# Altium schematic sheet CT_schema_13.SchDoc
size 741 x 377 mm
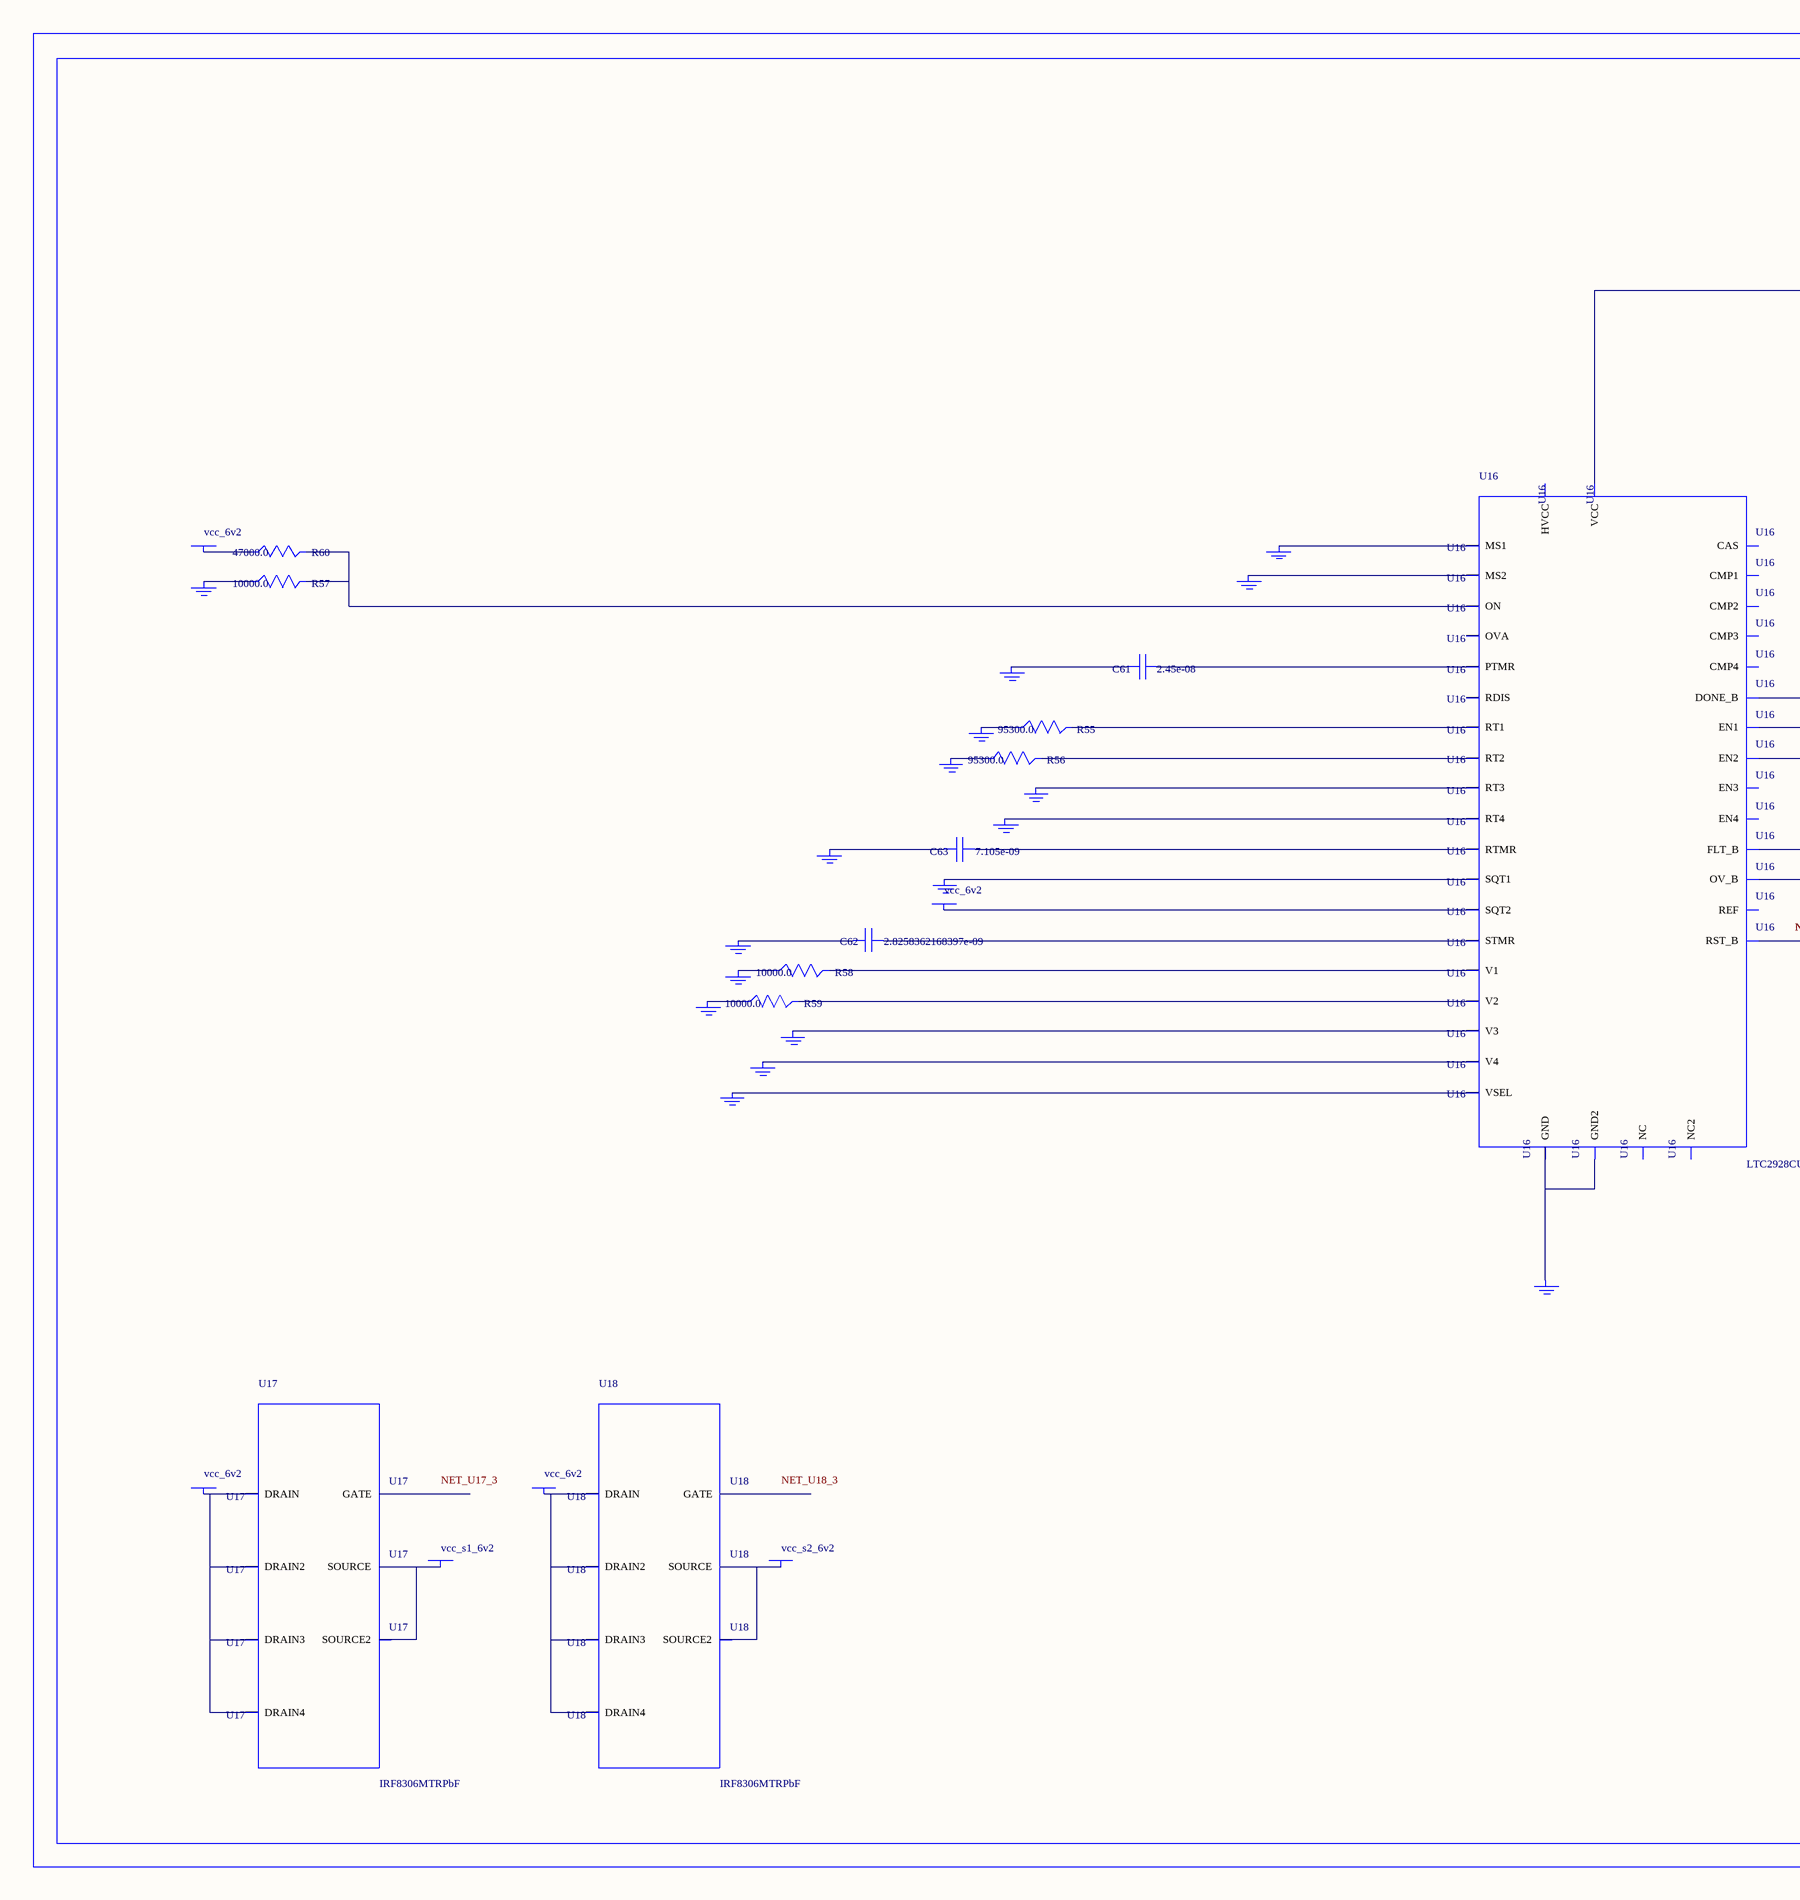
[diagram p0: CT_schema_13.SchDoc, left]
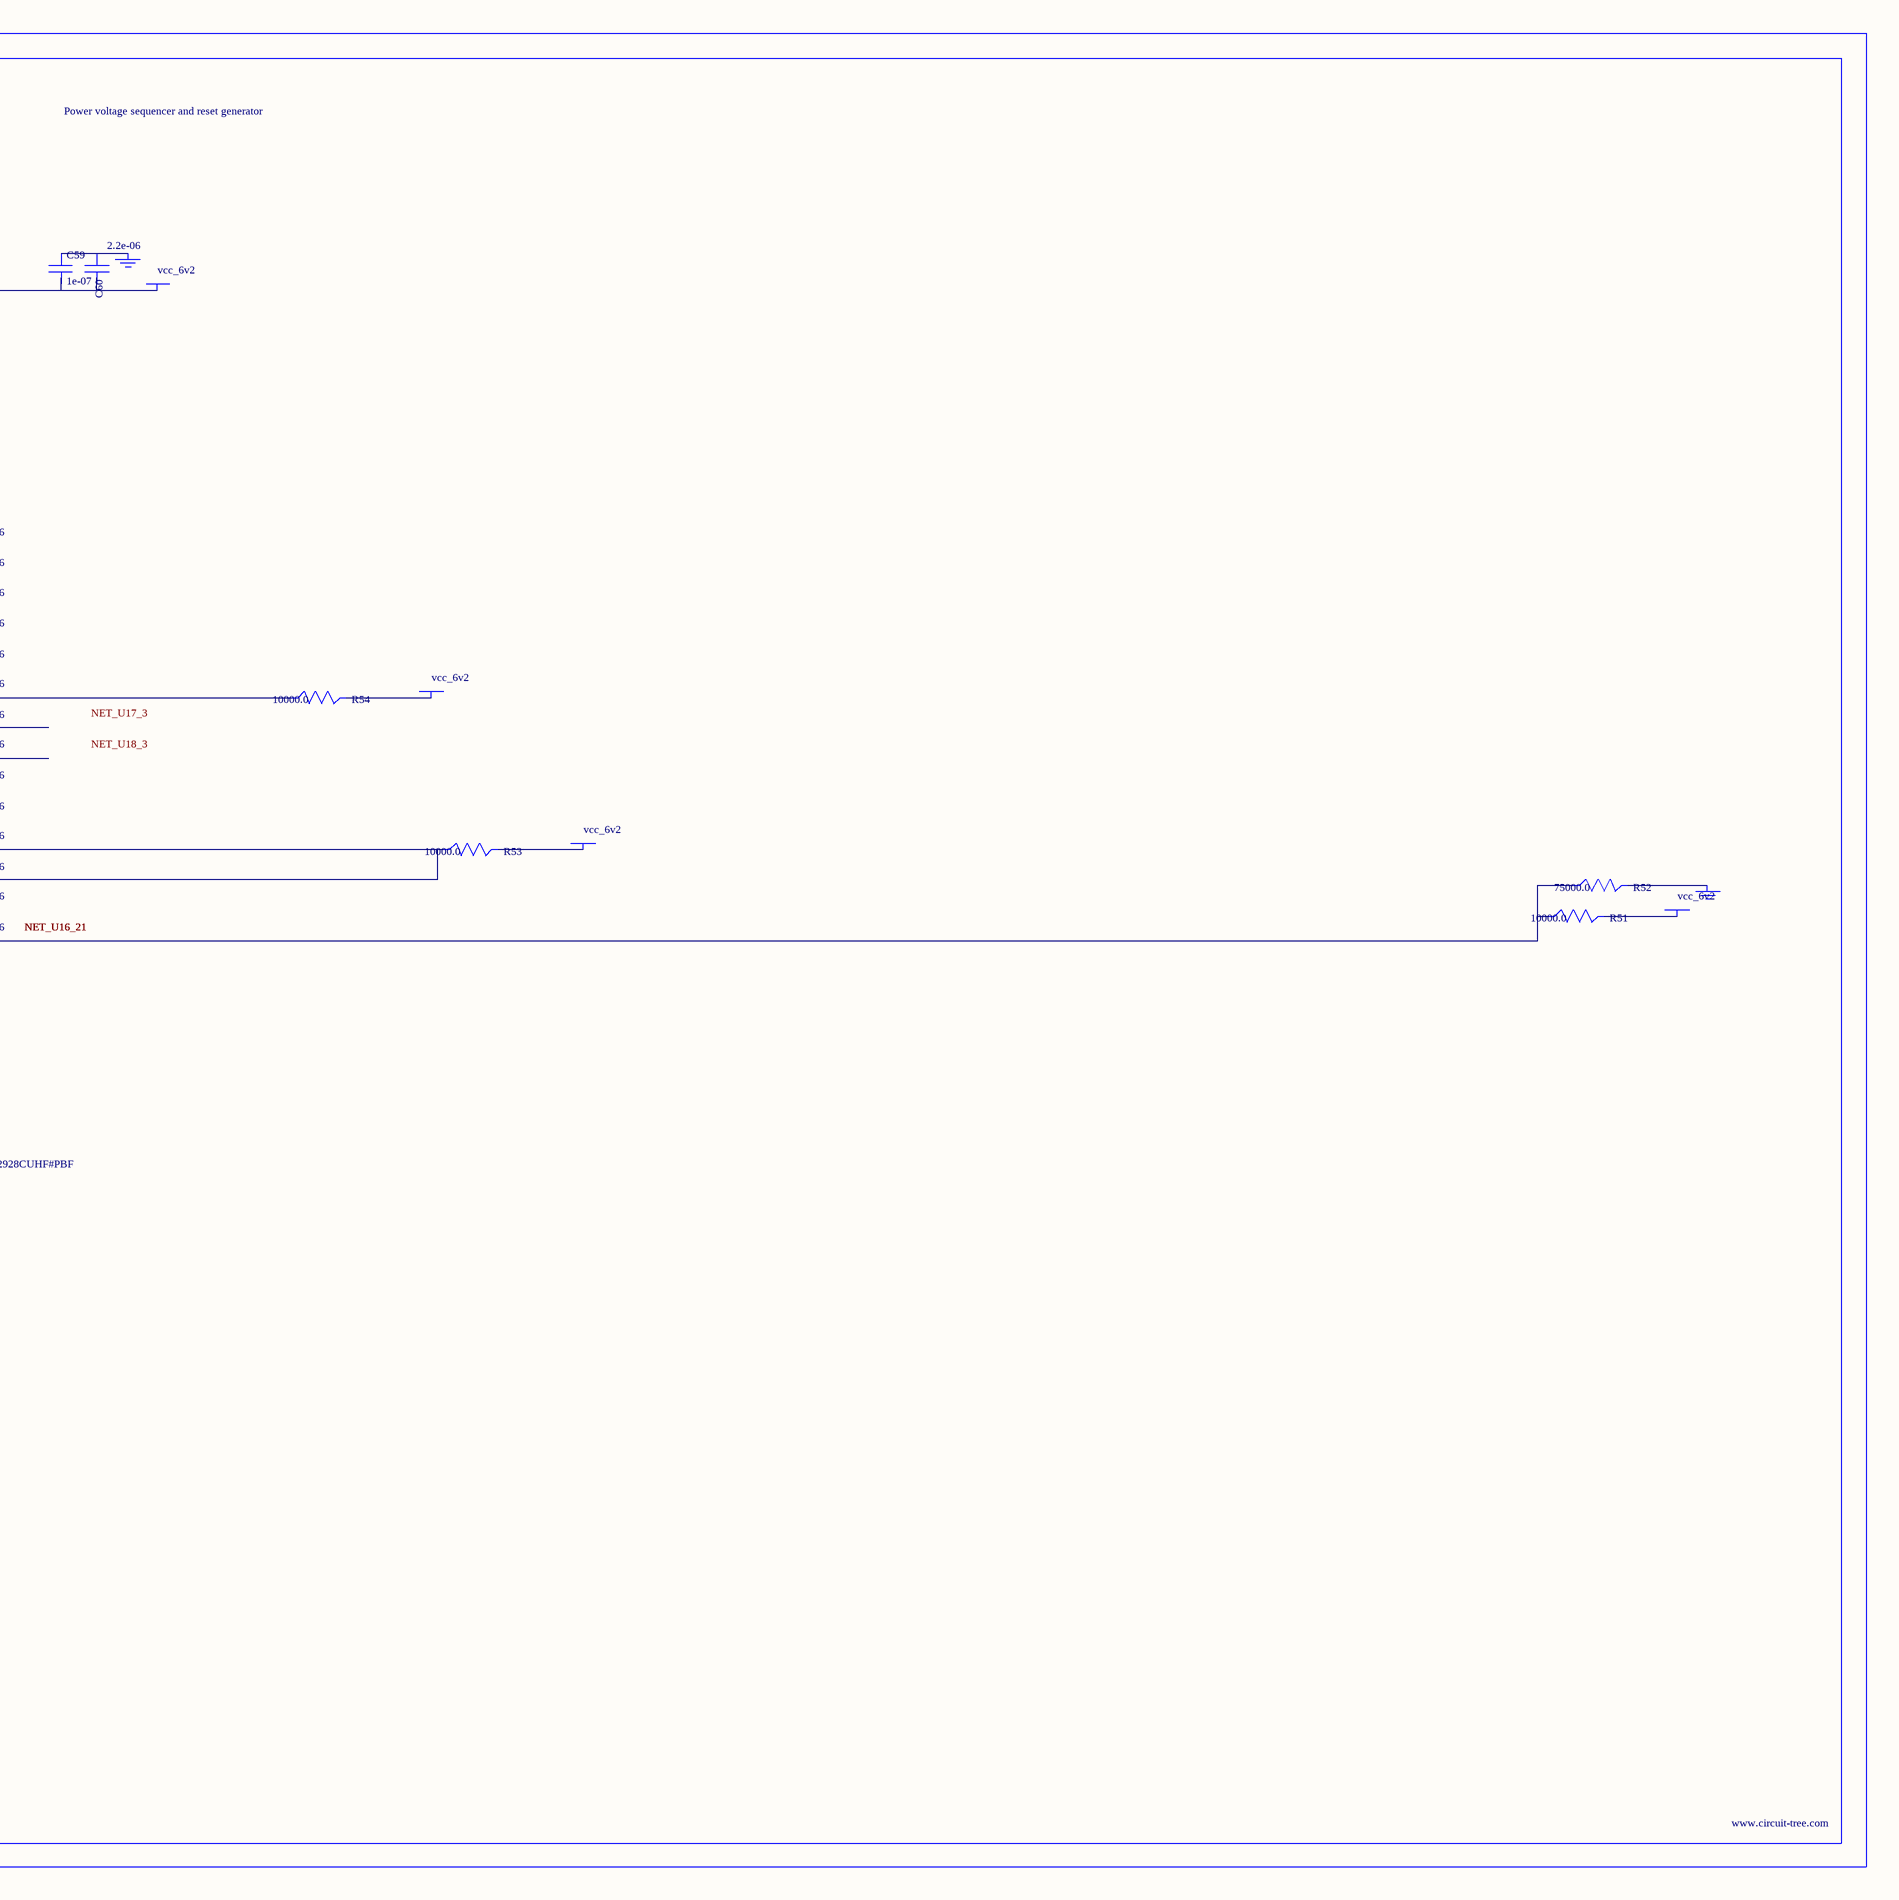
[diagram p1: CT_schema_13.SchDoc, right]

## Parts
BORDER12  (no value)
C59  1e-07  [C0402]
C60  2.2e-06  [C0603]
C61  2.45e-08  [R0603]
C62  2.8258362168397e-09  [R0603]
C63  7.105e-09  [R0603]
GND_INSTANCE_12_0  (no value)
GND_INSTANCE_12_1  (no value)
GND_INSTANCE_12_2  (no value)
GND_INSTANCE_12_3  (no value)
GND_INSTANCE_12_4  (no value)
GND_INSTANCE_12_5  (no value)
GND_INSTANCE_12_6  (no value)
GND_INSTANCE_12_7  (no value)
GND_INSTANCE_12_8  (no value)
GND_INSTANCE_12_9  (no value)
GND_INSTANCE_12_10  (no value)
GND_INSTANCE_12_11  (no value)
GND_INSTANCE_12_12  (no value)
GND_INSTANCE_12_13  (no value)
GND_INSTANCE_12_14  (no value)
GND_INSTANCE_12_15  (no value)
GND_INSTANCE_12_16  (no value)
GND_INSTANCE_12_17  (no value)
GND_INSTANCE_12_18  (no value)
POWER_INSTANCE_12_0  vcc_6v2
POWER_INSTANCE_12_1  vcc_6v2
POWER_INSTANCE_12_2  vcc_6v2
POWER_INSTANCE_12_3  vcc_6v2
POWER_INSTANCE_12_4  vcc_6v2
POWER_INSTANCE_12_5  vcc_6v2
POWER_INSTANCE_12_6  vcc_6v2
POWER_INSTANCE_12_7  vcc_s1_6v2
POWER_INSTANCE_12_8  vcc_6v2
POWER_INSTANCE_12_9  vcc_s2_6v2
R51  10000.0  [R0603]
R52  75000.0  [R0603]
R53  10000.0  [R0603]
R54  10000.0  [R0603]
R55  95300.0  [R0603]
R56  95300.0  [R0603]
R57  10000.0  [R0603]
R58  10000.0  [R0603]
R59  10000.0  [R0603]
R60  47000.0  [R0603]
U16  LTC2928CUHF#PBF  [QFN-38_UHF]
U17  IRF8306MTRPbF  [IRF8306MTRPBF]
U18  IRF8306MTRPbF  [IRF8306MTRPBF]

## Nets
NetC59_1: C59.1 C60.1 GND_INSTANCE_12_10.0(GND)
NetC59_2: C59.2 C60.2 POWER_INSTANCE_12_5.0(PWR) U16.22(VCC)
NetC61_1: C61.1 U16.27(PTMR)
NetC61_2: C61.2 GND_INSTANCE_12_13.0(GND)
NetC62_1: C62.1 U16.26(STMR)
NetC62_2: C62.2 GND_INSTANCE_12_12.0(GND)
NetC63_1: C63.1 U16.28(RTMR)
NetC63_2: C63.2 GND_INSTANCE_12_14.0(GND)
NetGND_INSTANCE_12_0_0: GND_INSTANCE_12_0.0(GND) R58.1
NetGND_INSTANCE_12_1_0: GND_INSTANCE_12_1.0(GND) R55.1
NetGND_INSTANCE_12_2_0: GND_INSTANCE_12_2.0(GND) R56.1
NetGND_INSTANCE_12_3_0: GND_INSTANCE_12_3.0(GND) U16.8(RT3)
NetGND_INSTANCE_12_4_0: GND_INSTANCE_12_4.0(GND) U16.9(RT4)
NetGND_INSTANCE_12_5_0: GND_INSTANCE_12_5.0(GND) U16.10(SQT1)
NetGND_INSTANCE_12_6_0: GND_INSTANCE_12_6.0(GND) U16.12(MS1)
NetGND_INSTANCE_12_7_0: GND_INSTANCE_12_7.0(GND) U16.13(MS2)
NetGND_INSTANCE_12_8_0: GND_INSTANCE_12_8.0(GND) R57.1
NetGND_INSTANCE_12_9_0: GND_INSTANCE_12_9.0(GND) R52.2
NetGND_INSTANCE_12_11_0: GND_INSTANCE_12_11.0(GND) U16.25(VSEL)
NetGND_INSTANCE_12_15_0: GND_INSTANCE_12_15.0(GND) U16.30(V4)
NetGND_INSTANCE_12_16_0: GND_INSTANCE_12_16.0(GND) U16.32(V3)
NetGND_INSTANCE_12_17_0: GND_INSTANCE_12_17.0(GND) R59.1
NetGND_INSTANCE_12_18_0: GND_INSTANCE_12_18.0(GND) U16.24(GND) U16.39(GND2)
NetPOWER_INSTANCE_12_0_0: POWER_INSTANCE_12_0.0(PWR) U16.11(SQT2)
NetPOWER_INSTANCE_12_1_0: POWER_INSTANCE_12_1.0(PWR) R60.1
NetPOWER_INSTANCE_12_2_0: POWER_INSTANCE_12_2.0(PWR) R54.2
NetPOWER_INSTANCE_12_3_0: POWER_INSTANCE_12_3.0(PWR) R53.2
NetPOWER_INSTANCE_12_4_0: POWER_INSTANCE_12_4.0(PWR) R51.2
NetPOWER_INSTANCE_12_6_0: POWER_INSTANCE_12_6.0(PWR) U17.1(DRAIN) U17.2(DRAIN2) U17.6(DRAIN3) U17.7(DRAIN4)
NetPOWER_INSTANCE_12_7_0: POWER_INSTANCE_12_7.0(PWR) U17.4(SOURCE) U17.5(SOURCE2)
NetPOWER_INSTANCE_12_8_0: POWER_INSTANCE_12_8.0(PWR) U18.1(DRAIN) U18.2(DRAIN2) U18.6(DRAIN3) U18.7(DRAIN4)
NetPOWER_INSTANCE_12_9_0: POWER_INSTANCE_12_9.0(PWR) U18.4(SOURCE) U18.5(SOURCE2)
NetR51_1: R51.1 R52.1 U16.21(RST_B)
NetR53_1: R53.1 U16.19(FLT_B) U16.20(OV_B)
NetR54_1: R54.1 U16.18(DONE_B)
NetR55_2: R55.2 U16.6(RT1)
NetR56_2: R56.2 U16.7(RT2)
NetR57_2: R57.2 R60.2 U16.16(ON)
NetR58_2: R58.2 U16.3(V1)
NetR59_2: R59.2 U16.38(V2)

Not connected (* = marked no-connect by the designer): U16 1(OVA) 2(EN1) 4(NC) 5(REF) 14(RDIS) 15(CAS) 17(NC2) 23(HVCC) 29(EN4) 31(EN3) 33(CMP3) 34(CMP4) 35(CMP1) 36(CMP2) 37(EN2); U17 3(GATE); U18 3(GATE)

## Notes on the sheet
- Labels drawn without touching a wire or pin: NET_U17_3, NET_U18_3

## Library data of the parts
BORDER12 = BORDER_PAGE12
C59 = C0402C104K3RACTU
C60 = GRM188R61H225KE1115D
C61 = C61
C62 = C62
C63 = C63
GND_INSTANCE_12_0-GND_INSTANCE_12_18 = GND
POWER_INSTANCE_12_0-POWER_INSTANCE_12_9 = PWR
R51 R53 R54 R57-R59 = RC0603JR-0710KL
R52 = RC0603JR-0775KL
R55 R56 = RC0603FR-0795K3L
R60 = RC0603JR-0747KL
